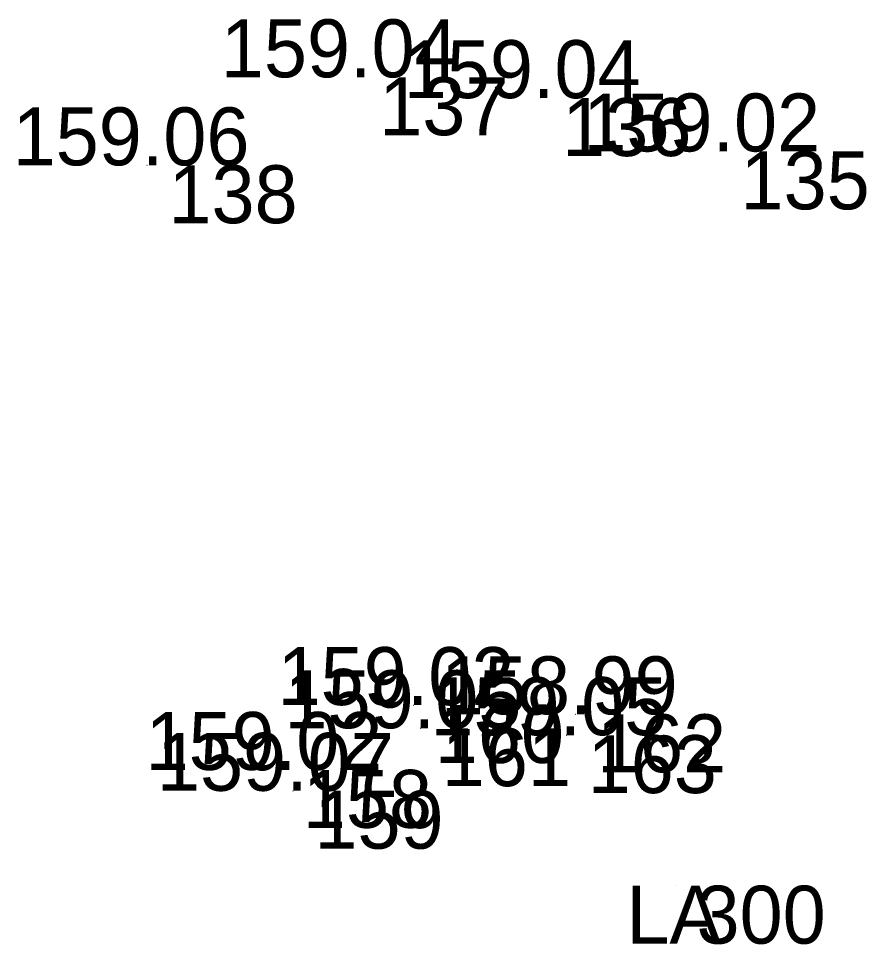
# Model space of a CAD drawing. Extents: x -583198 to -582878, y -1211024 to -1210637.
# Drawn here: x -583184.285 to -583180.623, y -1210970.404 to -1210966.406 of the extents above; entities that cross this region are included whole.
import ezdxf

# ---------------------------------------------------------------- set-up
doc = ezdxf.new("R2010")
doc.units = 0
for name, color, linetype in [('1   Kódy', 7, 'Continuous'), ('4   Body podrobné', 7, 'Continuous'), ('5   Body podrobné - čísla', 7, 'Continuous'), ('6   Body podrobné - výšky', 7, 'Continuous')]:
    doc.layers.add(name, color=color, linetype=linetype)

msp = doc.modelspace()

# ---------------------------------------------------------------- linework, layer by layer
at = {"layer": '4   Body podrobné'}
for p, q in [((-583182.82, -1210966.66), (-583182.819, -1210966.66)), ((-583182.03, -1210966.75), (-583182.029, -1210966.75)), ((-583181.26, -1210966.98), (-583181.259, -1210966.98)), ((-583183.73, -1210967.04), (-583183.729, -1210967.04)), ((-583182.58, -1210969.37), (-583182.579, -1210969.37)), ((-583181.88, -1210969.41), (-583181.879, -1210969.41)), ((-583182.55, -1210969.47), (-583182.549, -1210969.47)), ((-583181.92, -1210969.5), (-583181.919, -1210969.5)), ((-583183.15, -1210969.65), (-583183.149, -1210969.65)), ((-583183.1, -1210969.74), (-583183.099, -1210969.74)), ((-583181.45, -1210970.15), (-583181.449, -1210970.15))]:
    msp.add_line(p, q, dxfattribs=at)

# ---------------------------------------------------------------- texts
at = {"layer": '1   Kódy'}
msp.add_text('LA', height=0.25, dxfattribs=at).set_placement((-583181.66, -1210970.4))
at = {"layer": '5   Body podrobné - čísla'}
for s, p in [(' 137', (-583182.82, -1210966.91)), (' 136', (-583182.03, -1210967)), (' 135', (-583181.26, -1210967.23)), (' 138', (-583183.73, -1210967.29)), (' 160', (-583182.58, -1210969.62)), (' 162', (-583181.88, -1210969.66)), (' 161', (-583182.55, -1210969.72)), (' 163', (-583181.92, -1210969.75)), (' 158', (-583183.15, -1210969.9)), (' 159', (-583183.1, -1210969.99)), (' 300', (-583181.45, -1210970.4))]:
    msp.add_text(s, height=0.25, dxfattribs=at).set_placement(p)
at = {"layer": '6   Body podrobné - výšky'}
for s, p in [('159.04', (-583183.411, -1210966.66)), ('159.04', (-583182.621, -1210966.75)), ('159.02', (-583181.846, -1210966.98)), ('159.06', (-583184.31, -1210967.04)), ('159.02', (-583183.166, -1210969.37)), ('158.99', (-583182.461, -1210969.41)), ('159.05', (-583183.136, -1210969.47)), ('159.05', (-583182.506, -1210969.5)), ('159.02', (-583183.736, -1210969.65)), ('159.07', (-583183.687, -1210969.74))]:
    msp.add_text(s, height=0.25, dxfattribs=at).set_placement(p)

doc.saveas('drawing.dxf')
